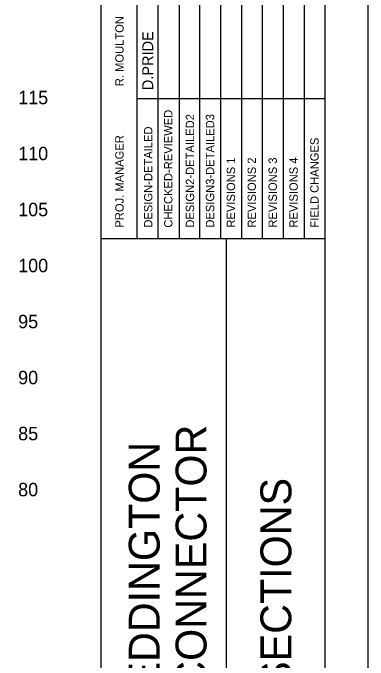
# Model space of a CAD drawing. Extents: x 1760610 to 1760954, y 442591 to 442811.
# Drawn here: x 1760918.8 to 1760950.4, y 442649 to 442706.8 of the extents above; entities that cross this region are included whole.
import ezdxf

# ---------------------------------------------------------------- set-up
doc = ezdxf.new("R2010")
doc.units = 0
for name, color, linetype in [('BORDER', 7, 'Continuous'), ('H_V ANNOTATION', 7, 'Continuous'), ('PLOT BOUNDARY', 7, 'Continuous')]:
    doc.layers.add(name, color=color, linetype=linetype)

msp = doc.modelspace()

# ---------------------------------------------------------------- linework, layer by layer
at = {"layer": 'BORDER'}
for p, q in [((1760926.614, 442596.665), (1760926.614, 442806.665)), ((1760926.614, 442686.671), (1760946.614, 442686.671)), ((1760937.796, 442616.671), (1760937.796, 442686.671))]:
    msp.add_line(p, q, dxfattribs=at)
msp.add_lwpolyline([(1760626.614, 442596.665), (1760946.614, 442596.665), (1760946.614, 442806.665), (1760626.614, 442806.665)], close=True, dxfattribs=at)
for points in [[(1760931.709, 442686.677), (1760931.709, 442721.671)], [(1760933.572, 442721.671), (1760933.572, 442686.677)], [(1760935.435, 442686.677), (1760935.435, 442721.671)], [(1760937.299, 442686.677), (1760937.299, 442721.671)], [(1760939.162, 442686.677), (1760939.162, 442721.671)], [(1760941.026, 442686.677), (1760941.026, 442721.671)], [(1760942.889, 442686.677), (1760942.889, 442721.671)], [(1760944.752, 442686.677), (1760944.752, 442721.671)], [(1760929.845, 442686.677), (1760929.845, 442720.259)], [(1760929.844, 442699.171), (1760946.614, 442699.171)]]:
    msp.add_lwpolyline(points, dxfattribs=at)
at = {"layer": 'PLOT BOUNDARY'}
msp.add_lwpolyline([(1760610.427, 442590.547), (1760950.427, 442590.547), (1760950.427, 442810.547), (1760610.427, 442810.547)], close=True, dxfattribs=at)

# ---------------------------------------------------------------- texts
at = {"layer": 'BORDER'}
for s, height, p in [('R. MOULTON', 0.7455, (1760928.623, 442700.276)), ('D.PRIDE', 0.9691, (1760931.26, 442699.917)), ('CHECKED-REVIEWED', 0.7455, (1760932.976, 442687.647)), ('DESIGN2-DETAILED2', 0.7455, (1760934.914, 442687.647)), ('DESIGN3-DETAILED3', 0.7455, (1760936.703, 442687.647)), ('DESIGN-DETAILED', 0.7455, (1760931.187, 442687.647)), ('PROJ. MANAGER', 0.7455, (1760928.622, 442687.647)), ('FIELD CHANGES', 0.7455, (1760946.019, 442687.647)), ('REVISIONS 1', 0.7455, (1760938.566, 442687.647)), ('REVISIONS 2', 0.7455, (1760940.429, 442687.647)), ('REVISIONS 3', 0.7455, (1760942.293, 442687.647)), ('REVISIONS 4', 0.7455, (1760944.156, 442687.647)), ('1-395/ROUTE 9 CONNECTOR', 2.75575, (1760936.016, 442618.865)), ('BREWER TO EDDINGTON', 2.75575, (1760931.837, 442623.074)), ('CROSS SECTIONS', 2.75575, (1760943.583, 442632.339))]:
    msp.add_text(s, height=height, rotation=90, dxfattribs=at).set_placement(p)
at = {"layer": 'H_V ANNOTATION'}
for s, p in [('115', (1760919.214, 442698.665)), ('110', (1760919.214, 442693.665)), ('105', (1760919.214, 442688.665)), ('100', (1760919.214, 442683.665)), ('95', (1760919.214, 442678.665)), ('90', (1760919.214, 442673.665)), ('85', (1760919.214, 442668.665)), ('80', (1760919.214, 442663.665))]:
    msp.add_text(s, height=1.2, dxfattribs=at).set_placement(p)

doc.saveas('drawing.dxf')
